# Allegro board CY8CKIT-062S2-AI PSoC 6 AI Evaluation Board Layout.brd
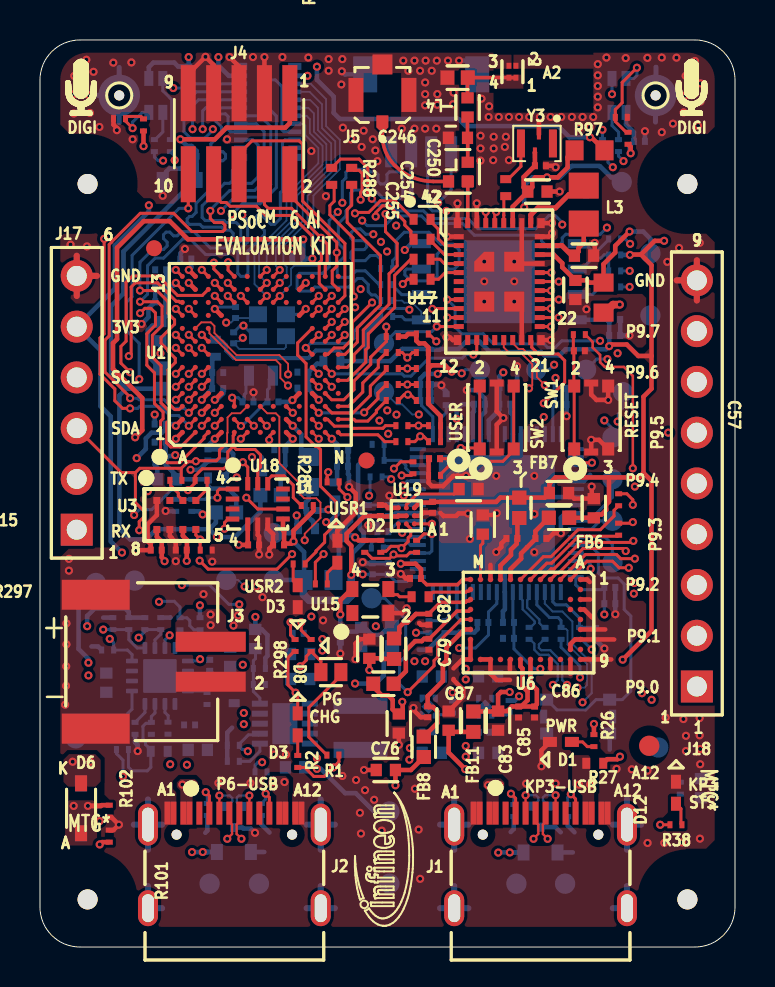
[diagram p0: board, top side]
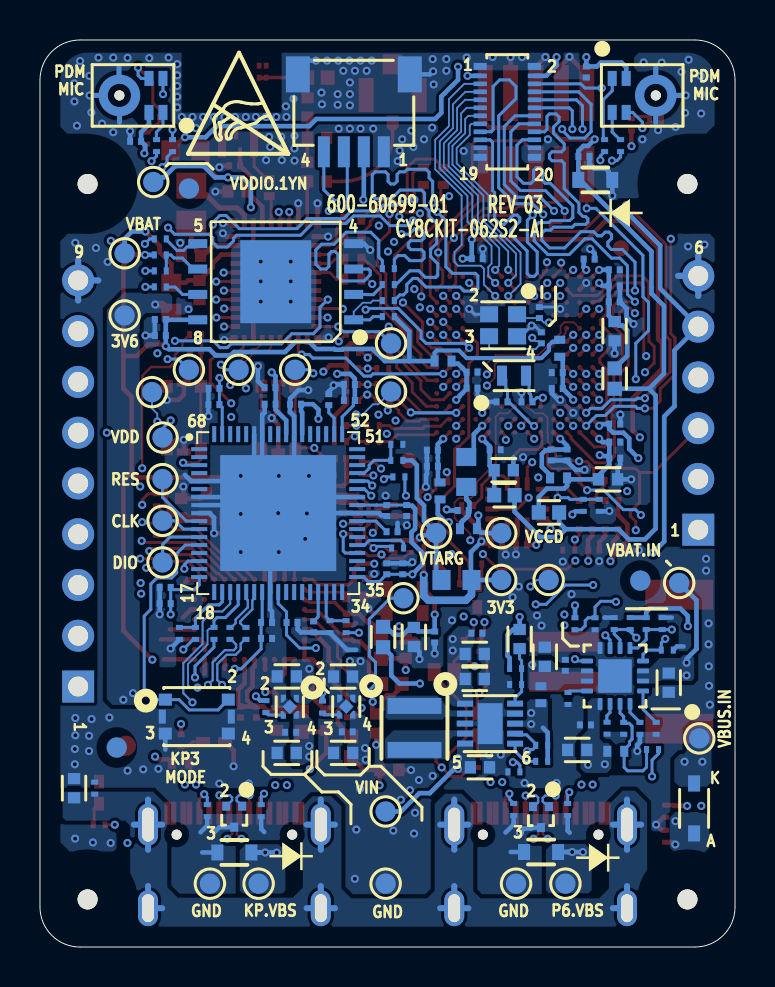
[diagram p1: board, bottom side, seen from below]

Outline 34.76 x 45.38 mm; copper layers: TOP, L02_GND1, L03_SIG1, L04_SIG2, L05_GND2, BOTTOM. Coordinates in mm from the lower left corner of the outline.
Outline path: 0,43.38 arc(0.59,44.8) 2,45.38 32.76,45.38 arc(34.18,44.8) 34.76,43.38 34.76,2 arc(34.18,0.59) 32.76,0 2,0 arc(0.59,0.59) 0,2 0,43.38

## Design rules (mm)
constraint set DEFAULT: min track width 0.15
net group DP_KP_USB_D: nets KP_USB_DM KP_USB_DP
net group KP_USB: nets N17581130 N17581131
net group P6_USB: nets P6_USB_DM P6_USB_DP
net group QSPI_DATA0_P11_6: nets N17289581 QSPI_DATA0_P11_6
net group QSPI_DATA1_P11_5: nets N17289597 QSPI_DATA1_P11_5
net group QSPI_DATA2_P11_4: nets N17289613 QSPI_DATA2_P11_4
net group QSPI_DATA3_P11_3: nets N17289629 QSPI_DATA3_P11_3
net group DEFAULT_1_5W: nets N17073640 N17073643 N17073646 N17073649 N17073652 N17073655 P5LP_XRES QSPI_CLK_P11_7 SDIO_CLK SDIO_CMD SDIO_DATA0 SDIO_DATA1 SDIO_DATA2 SDIO_DATA3
net group NON-IMPEDANCE: nets N17332695 N17332709 P8_0 P8_1 P8_2 P8_3 P8_4 P8_5 P9_0 P9_1 P9_2 P9_3 P9_4 P9_5 P9_6 P9_7
net group POWER: nets GND_EARTH KP_VBUS N17065875 N17305257 N17305261 N17462113 USB_V_SENSE VBACKUP VBAT VBAT_IN VBUCK VBUS_IN VCC_1V8 VCC_3V3 VCC_3V6 VCCD VDD_NS VDDA VDDA_RADAR VDDD VDDD_RADAR VDDIO0 VDDIO2 VDDIO_1YN VDDLF_RADAR VDDPLL_RADAR VDDRF_RADAR VDDUSB VDDVCO_RADAR VIN VREF VTARG_MEAS
net group QSPI_CLK_P11_7: nets N17531826
net group RF_50E_L2: nets ANT0 ANT1 ANT2 N17332525
net group SDHC: nets SDHC_CLK SDHC_CMD SDHC_DATA00 SDHC_DATA01 SDHC_DATA02 SDHC_DATA03 SDHC_DATA10 SDHC_DATA11 SDHC_DATA12 SDHC_DATA13
nets with their own width: min track width 0.229; nets GND_SIGNAL

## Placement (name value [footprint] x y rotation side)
A2  2450AT07A0100T  [ANT_2450AT07A0100]  23.63 43.79 0 top
C1  0.1uF  [CAPC0603_0201N]  8.49 14.09 90 bottom
C2  4.7uF  [CAPC1005_0402N]  9.51 14.52 90 bottom
C3  1uF  [CAPC1005_0402N]  7.89 9.86 0 bottom
C4  0.1uF  [CAPC0603_0201N]  7.48 11.11 0 bottom
C5  4.7uF  [CAPC1005_0402N]  3.32 13.23 270 bottom
C6  10nF  [CAPC1005_0402N]  33.06 7.95 90 bottom
C7  1uF  [CAPC1005_0402N]  19.6 9.71 0 bottom
C8  0.1uF  [CAPC0603_0201N]  19.39 10.76 0 bottom
C9  10uF  [CAPC1005_0402N]  12.76 8.99 180 bottom
C10  10uF  [CAPC1005_0402N]  13.02 13.41 180 bottom
C11  10uF  [CAPC1005_0402N]  13.02 14.66 180 bottom
C12  1uF  [CAPC1005_0402N]  19.6 13.53 0 bottom
C13  1uF  [CAPC1005_0402N]  22.42 9.71 0 bottom
C14  0.1uF  [CAPC0603_0201N]  22.22 10.74 0 bottom
C15  1uF  [CAPC1005_0402N]  22.41 13.54 0 bottom
C16  1uF  [CAPC0603_0201N]  23.43 15.44 180 bottom
C17  0.1uF  [CAPC0603_0201N]  23.43 16.24 180 bottom
C18  1uF  [CAPC0603_0201N]  16.62 18.92 90 bottom
C19  0.1uF  [CAPC0603_0201N]  17.42 18.92 90 bottom
C20  1uF  [CAPC0603_0201N]  16.42 21.84 270 bottom
C21  0.1uF  [CAPC0603_0201N]  17.42 21.84 270 bottom
C22  1uF  [CAPC0603_0201N]  28.5 17.18 0 bottom
C23  0.1uF  [CAPC0603_0201N]  28.5 17.99 0 bottom
C24  1uF  [CAPC0603_0201N]  20.32 27.39 90 bottom
C25  1uF  [CAPC0603_0201N]  22.16 16.24 180 bottom
C26  0.1uF  [CAPC0603_0201N]  21.98 27.16 0 bottom
C27  1uF  [CAPC0603_0201N]  26.06 27.95 0 bottom
C28  0.1uF  [CAPC0603_0201N]  26.06 27.14 0 bottom
C29  1uF  [CAPC0603_0201N]  19.29 28.14 0 bottom
C30  0.1uF  [CAPC0603_0201N]  19.29 27.34 0 bottom
C31  1uF  [CAPC0603_0201N]  23.26 27.99 0 bottom
C32  0.1uF  [CAPC0603_0201N]  23.25 27.16 0 bottom
C33  1uF  [CAPC0603_0201N]  17.15 20.78 180 bottom
C34  1uF  [CAPC0603_0201N]  21.07 16.02 270 bottom
C35  4.7uF  [CAPC0603_0201N]  13.6 21.84 0 bottom
C36  10uF  [CAPC1005_0402N]  11.57 23.86 180 bottom
C37  1uF  [CAPC0603_0201N]  7.29 34.42 180 bottom
C38  10uF  [CAPC1005_0402N]  6.35 23.4 180 bottom
C39  1uF  [CAPC0603_0201N]  6.01 26.16 180 bottom
C40  10uF  [CAPC1005_0402N]  6.02 30.81 270 bottom
C41  0.1uF  [CAPC0603_0201N]  15.14 24.86 0 bottom
C42  1uF  [CAPC0603_0201N]  15.13 24.05 0 bottom
C43  0.1uF  [CAPC0603_0201N]  8.4 24.62 270 bottom
C44  1uF  [CAPC0603_0201N]  9.2 24.62 270 bottom
C45  0.1uF  [CAPC0603_0201N]  13.15 27.96 180 bottom
C46  1uF  [CAPC0603_0201N]  13.15 28.76 180 bottom
C47  0.1uF  [CAPC0603_0201N]  6.04 33.88 180 bottom
C48  1uF  [CAPC0603_0201N]  6.04 32.28 180 bottom
C49  0.1uF  [CAPC0603_0201N]  6.04 33.08 180 bottom
C50  0.1uF  [CAPC0603_0201N]  6.01 25.26 180 bottom
C51  1uF  [CAPC0603_0201N]  6.01 24.46 180 bottom
C52  0.1uF  [CAPC0603_0201N]  12.89 34.44 180 bottom
C53  0.1uF  [CAPC0603_0201N]  8.89 27.94 0 bottom
C54  1uF  [CAPC0603_0201N]  8.89 28.74 0 bottom
C55  0.1uF  [CAPC0603_0201N]  12 24.88 180 bottom
C56  1uF  [CAPC0603_0201N]  7.56 39.56 180 bottom
C57  0.1uF  [CAPC0603_0201N]  26.98 29.83 0 top
C58  0.1uF  [CAPC0603_0201N]  19.73 24.43 180 top
C60  22pF  [CAPC0603_0201N]  10.4 27.28 180 bottom
C61  22pF  [CAPC0603_0201N]  11.65 27.28 180 bottom
C62  10pF  [CAPC0603_0201N]  9.78 31.74 90 bottom
C63  10pF  [CAPC0603_0201N]  9.69 30.48 90 bottom
C66  0.1uF  [CAPC0603_0201N]  5.81 19.86 180 top
C67  0.1uF  [CAPC0603_0201N]  7.07 19.86 180 top
C68  0.1uF  [CAPC0603_0201N]  7.44 43.78 270 bottom
C71  0.1uF  [CAPC0603_0201N]  29.98 40.31 0 bottom
C72  10uF  [CAPC1005_0402N]  27.7 21.95 90 top
C73  1uF  [CAPC0603_0201N]  25.06 20.44 0 top
C74  10uF  [CAPC1005_0402N]  25.96 22.71 0 top
C75  1uF  [CAPC0603_0201N]  23.6 20.44 180 top
C76  10uF  [CAPC1005_0402N]  17.3 8.86 180 top
C77  1uF  [CAPC0603_0201N]  19.39 11.77 270 top
C78  10uF  [CAPC1005_0402N]  17.95 11.18 270 top
C79  1uF  [CAPC0603_0201N]  19.45 15.15 270 top
C80  0.47uF  [CAPC1005_0402N]  22.15 21.14 270 top
C81  10uF  [CAPC1005_0402N]  16.47 14.92 90 top
C82  1uF  [CAPC0603_0201N]  19.45 16.4 270 top
C83  10uF  [CAPC1005_0402N]  22.91 11.32 270 top
C84  1uF  [CAPC0603_0201N]  18.78 18.44 180 top
C85  1uF  [CAPC0603_0201N]  23.94 11.76 270 top
C86  1uF  [CAPC0603_0201N]  24.74 11.76 270 top
C87  10uF  [CAPC1005_0402N]  20.44 11.32 90 top
C88  10uF  [CAPC1005_0402N]  16.06 15.51 270 bottom
C89  1uF  [CAPC0603_0201N]  15.02 15.51 270 bottom
C92  0.1uF  [CAPC0603_0201N]  28.74 31.4 0 bottom
C93  1uF  [CAPC0603_0201N]  28.74 30.6 0 bottom
C99  2.2uF  [CAPC1005_0402N]  24.88 37.8 0 top
C115  0.1uF  [CAPC0603_0201N]  17.02 21.84 90 top
C116  0.1uF  [CAPC0603_0201N]  10.68 20.12 180 top
C119  0.1uF  [CAPC0603_0201N]  19.63 22 270 top
C121  0.1uF  [CAPC0603_0201N]  11.93 20.12 180 top
C245  2.2uF  [CAPC1005_0402N]  21.44 22.91 0 top
C246  6.8pF  [CAPC1005_0402N]  21.39 42 90 top
C247  4.7uF  [CAPC1005_0402N]  26.78 32.87 270 top
C248  4.7uF  [CAPC1005_0402N]  27.21 34.59 0 top
C249  1uF  [CAPC0603_0201N]  25.03 39.09 0 top
C250  1.2pF  [CAPC1005_0402N]  20.9 40.48 180 top
C253  150pF  [CAPC1005_0402N]  10.77 15.41 270 bottom
C254  6.8pF  [CAPC1005_0402N]  21.39 38.78 90 top
C255  6.8pF  [CAPC1005_0402N]  20.91 38.3 0 top
C256  0.1uF  [CAPC0603_0201N]  12.91 15.7 180 bottom
D1  5988A10107F  [LEDC1005_0402Q]  26.05 10.26 180 top
D2  5988A10107F  [LEDC1005_0402Q]  14.87 19.78 90 top
D3  5988A10107F  [LEDC1005_0402Q]  12.89 17.55 270 top
D4  T5V0S5A-7  [SODFL1608X77N]  9.7 4.75 180 bottom
D5  BAS3010B03WE6327HTSA1  [SOD2512X110N]  2.05 6.93 270 bottom
D6  BAS3010B03WE6327HTSA1  [SOD2512X110N]  2.06 6.94 270 top
D8  LTST-C281KGKT  [LEDC1005X35N_GN_LITEON]  14.55 13.75 0 top
D9  ESD5V0D5-TP  [SODFL1608X77N]  6.99 38.38 0 bottom
D10  T5V0S5A-7  [SODFL1608X77N]  25.04 4.73 180 bottom
D11  5988A10107F  [LEDC1005_0402Q]  12.89 11.14 90 top
D12  5988A10107F  [LEDC1005_0402Q]  31.81 7.72 90 top
FB3  600 OHM  [INDC1005_0402M]  11.53 22.6 180 bottom
FB4  600 OHM  [INDC1005_0402M]  9.31 21.74 180 bottom
FB5  600 OHM  [INDC1005_0402M]  6.02 28.44 270 bottom
FB6  600 OHM  [INDC1005_0402M]  25.96 21.48 180 top
FB7  600 OHM  [INDC1005_0402M]  23.97 21.98 270 top
FB8  600 OHM  [INDC1005_0402M]  19.19 10.02 90 top
FB9  600 OHM  [INDC1005_0402M]  17.18 13.17 0 top
FB10  600 OHM  [INDC1005_0402M]  17.71 14.92 90 top
FB11  600 OHM  [INDC1005_0402M]  21.68 11.27 90 top
FB12  600 OHM  [INDC1005_0402M]  17.6 15.51 90 bottom
J1  629722000214  [GCT_USB4105-GF-A]  25.04 3.02 0 top
J2  629722000214  [GCT_USB4105-GF-A]  9.72 3.02 0 top
J3  620102131822  [JST_S2B-PH-SM4-TB-LF-SN]  5.09 14.28 90 top
J4  HDR 5x2  [SAMT_FTSH-105-XX-X-DV-K]  9.96 40.69 180 top
J5  A-1JB  [AMP_A-1JB_ALT1]  17.13 42.63 0 top
J15  DF40C-20DP-0.4V(51)  [HIROSE_DF40C-20DP-0P4V]  11.39 41.79 270 bottom
J16  665104131822  [JST_SM04B-SRSS-TB]  19.07 42.24 0 bottom
J17  PRPC006SFAN-RC  [SULLINS_PRPC006SFAN-RC]  1.84 20.88 90 top
J18  PRPC009SFAN-RC  [SULLINS_PRPC009SFAN-RC]  32.85 13.03 90 top
L1  2.2uH  [IND_NR3015T2R2M]  16.03 10.96 270 bottom
L2  2.2uH  [INDC1608_0603N]  13.44 23.77 270 bottom
L3  2.2uH  [INDC2012_0805N]  27.2 37.14 90 top
L4  6.8nH  [INDC1005_0402M]  20.89 43.5 180 top
NOREF  -  []  6.14 38.38 0 top
NOREF#2  -  []  8.47 6.7 0 top
NOREF#3  -  []  17.57 39.79 0 top
NOREF#4  -  []  10.53 30.23 0 top
NOREF#5  -  []  4.45 12.01 0 top
NOREF#6  -  []  1.29 10.33 90 top
NOREF#7  -  []  11 10.18 0 top
NOREF#8  -  []  10.95 9.88 90 top
NOREF#9  -  []  16.27 43.66 0 top
NOREF#10  -  []  21.99 28.07 0 top
NOREF#11  -  []  17.68 20.93 90 top
NOREF#12  -  []  1.32 5.98 0 top
NOREF#13  -  []  2.79 10.93 90 top
NOREF#14  -  [unnamed#2]  32.38 38.18 0 top
NOREF#15  -  []  2.6 44.15 0 top
NOREF#16  -  []  8.07 20.62 90 top
NOREF#17  -  []  7.97 6.7 0 top
NOREF#18  -  []  1.32 5.98 90 top
NOREF#19  -  []  16.03 9.86 90 top
NOREF#20  -  []  26.72 28.07 0 top
NOREF#21  -  []  20.72 1.94 90 top
NOREF#22  -  []  25.19 11.53 0 top
NOREF#23  -  []  26.2 18.72 90 top
NOREF#24  -  []  20.57 6.69 0 top
NOREF#25  -  []  1.84 28.5 90 top
NOREF#26  -  []  9.39 23.16 0 top
NOREF#27  -  []  23.29 6.7 0 top
NOREF#28  -  []  9.63 22.91 0 top
NOREF#29  -  []  17.68 20.93 0 top
NOREF#30  -  []  18.65 19.46 90 top
NOREF#31  -  []  3.11 22 0 top
NOREF#32  -  []  8.54 13.28 90 top
NOREF#33  -  []  25.27 10.08 90 top
NOREF#34  -  []  18.72 21.17 90 top
NOREF#35  -  []  22.84 24.77 90 top
NOREF#36  -  []  25.34 10.68 90 top
NOREF#37  -  []  5.4 1.94 0 top
NOREF#38  -  []  2.79 10.93 90 top
NOREF#39  -  []  12.68 28.48 90 top
NOREF#40  -  []  14.19 -0.66 90 top
NOREF#41  -  []  14.48 9.41 90 top
NOREF#42  -  []  25.69 4.31 90 top
NOREF#43  -  []  26.03 18.39 0 top
NOREF#44  -  []  17.57 39.79 90 top
NOREF#45  -  []  32.15 36.99 90 top
NOREF#46  -  []  7.55 12.01 90 top
NOREF#47  -  []  21.39 24.84 90 top
NOREF#48  -  []  29.51 -0.66 90 top
NOREF#49  -  []  5.25 6.69 0 top
NOREF#50  -  [unnamed#2]  2.38 2.38 0 top
NOREF#51  -  []  5.4 1.94 90 top
NOREF#52  -  []  4.6 13.31 90 top
NOREF#53  -  []  5.85 20.89 90 top
NOREF#54  -  []  17.57 39.79 0 top
NOREF#55  -  []  25.69 5.16 0 top
NOREF#56  -  []  29.51 -0.66 90 top
NOREF#57  -  []  2.6 40.07 90 top
NOREF#58  -  []  4.6 14.31 0 top
NOREF#59  -  [unnamed#2]  30.47 10.07 0 top
NOREF#60  -  []  0 43.38 0 top
NOREF#61  -  []  6.34 37.95 0 top
NOREF#62  -  []  14.48 9.41 0 top
NOREF#63  -  []  21.53 16.39 90 top
NOREF#64  -  []  17.52 16.51 90 top
NOREF#65  -  []  16.07 44.36 0 top
NOREF#66  -  []  25.34 12.38 0 top
NOREF#67  -  []  21.2 25.22 0 top
NOREF#68  -  []  10.35 5.18 90 top
NOREF#69  -  []  15.05 13.5 90 top
NOREF#70  -  []  2.05 5.68 90 top
NOREF#71  -  []  10.9 30.56 90 top
NOREF#72  -  []  22.07 40.11 90 top
NOREF#73  -  []  14.05 14 0 top
NOREF#74  -  []  10.95 12.48 0 top
NOREF#75  -  []  12.39 20.91 90 top
NOREF#76  -  []  32.85 20.65 90 top
NOREF#77  -  []  25.27 12.98 0 top
NOREF#78  -  []  10.39 23.18 0 top
NOREF#79  -  []  15.52 18.11 0 top
NOREF#80  -  []  146.08 294.67 0 top
NOREF#81  -  []  2.78 5.99 90 top
NOREF#82  -  []  -21.25 -36.06 0 top
NOREF#83  -  []  27.57 24.77 90 top
NOREF#84  -  []  15.62 16.71 90 top
NOREF#85  -  []  26.72 24.92 90 top
NOREF#86  -  []  18.32 21.97 0 top
NOREF#87  -  []  26.12 24.84 90 top
NOREF#88  -  []  21.39 28.14 0 top
NOREF#89  -  []  1.29 18.23 0 top
NOREF#90  -  []  26.12 28.14 0 top
NOREF#91  -  []  32.15 41.07 0 top
NOREF#92  -  []  14.19 -0.66 90 top
NOREF#93  -  []  15.62 16.71 0 top
NOREF#94  -  []  10.35 5.18 0 top
NOREF#95  -  []  34.13 0.54 0 top
NOREF#96  -  []  5.57 22.62 0 top
NOREF#97  -  [unnamed#2]  2.38 38.18 0 top
NOREF#98  -  []  20.72 1.94 0 top
NOREF#99  -  []  10.9 31.66 0 top
NOREF#100  -  []  1.33 5.99 0 top
NOREF#101  -  []  2.38 0 90 top
NOREF#102  -  []  6.34 37.95 90 top
NOREF#103  -  []  8.85 4.75 0 top
NOREF#104  -  []  2.06 5.69 90 top
NOREF#105  -  []  122.33 85.74 0 top
NOREF#106  -  []  6.5 20.89 0 top
NOREF#107  -  [unnamed#2]  32.38 2.38 0 top
NOREF#108  -  []  34.12 14.15 0 top
NOREF#109  -  []  13.5 10.68 90 top
NOREF#110  -  []  21.99 24.92 90 top
NOREF#111  -  []  24.19 4.73 0 top
NOREF#112  -  []  23.79 6.7 0 top
NOREF#113  -  []  5.25 12.16 90 top
NOREF#114  -  []  57.28 11.61 90 top
NOREF#115  -  [unnamed#2]  27.31 37.95 180 bottom
NOREF#116  -  [unnamed#2]  30.92 9.98 180 bottom
NOREF#117  -  [unnamed#2]  4.74 18.33 180 bottom
R1  1K  [RESC0603_0201N]  14.65 9.6 0 top
R2  1K  [RESC0603_0201N]  12.89 9.29 270 top
R3  10K  [RESC0603_0201N]  5.24 16.18 90 bottom
R4  10K  [RESC0603_0201N]  4.44 16.18 90 bottom
R5  5.1K  [RESC0603_0201N]  26.4 6.83 270 bottom
R6  5.1K  [RESC0603_0201N]  23.69 6.83 270 bottom
R7  100K  [RESC0603_0201N]  32.03 7.95 90 bottom
R8  10K  [RESC0603_0201N]  3.94 10.94 90 bottom
R9  10K  [RESC0603_0201N]  6.4 10.95 90 bottom
R10  10K  [RESC0603_0201N]  3.39 14.86 0 bottom
R11  10K  [RESC0603_0201N]  6.04 16.18 270 bottom
R12  10K  [RESC0603_0201N]  3.64 16.18 270 bottom
R13  10K  [RESC1005_0402N]  5.96 9.79 0 bottom
R14  3.01K  [RESC0603_0201N]  5.57 10.94 270 bottom
R15  1K  [RESC0603_0201N]  8.35 12.44 270 bottom
R16  4.7K  [RESC0603_0201N]  4.76 10.94 270 bottom
R17  5.1K  [RESC0603_0201N]  11.07 6.88 270 bottom
R18  5.1K  [RESC0603_0201N]  8.37 6.88 270 bottom
R19  4.7K  [RESC0603_0201N]  20.63 12.01 270 bottom
R20  4.7K  [RESC0603_0201N]  9.67 9.29 0 bottom
R21  560K  [RESC0603_0201N]  10.97 13.94 180 bottom
R22  4.7K  [RESC0603_0201N]  9.67 10.09 0 bottom
R23  90.9K  [RESC0603_0201N]  10.97 13.14 0 bottom
R24  4.7K  [RESC0603_0201N]  11.06 8.76 0 bottom
R25  4.7K  [RESC0603_0201N]  23.46 12.03 270 bottom
R26  1K  [RESC0603_0201N]  27.71 10.33 270 top
R27  0 OHM  [RESC1005_0402N]  27.75 9.19 180 top
R28  49.9K  [RESC0603_0201N]  16.91 24.35 0 bottom
R29  49.9K  [RESC0603_0201N]  16.91 25.15 0 bottom
R30  15K  [RESC0603_0201N]  19.45 16.03 90 bottom
R31  30K  [RESC0603_0201N]  20.25 16.03 90 bottom
R33  15K  [RESC0603_0201N]  26.99 15.69 90 bottom
R34  4.7K  [RESC0603_0201N]  26.06 15.69 270 bottom
R35  22 OHM  [RESC0603_0201N]  25.26 15.69 90 bottom
R36  30K  [RESC0603_0201N]  27.79 15.69 90 bottom
R37  22 OHM  [RESC0603_0201N]  24.46 15.69 90 bottom
R38  560 OHM  [RESC0603_0201N]  31.81 6.12 180 top
R39  0 OHM  [RESC1608_0603N]  13.93 18.37 0 bottom
R40  0 OHM  [RESC1005_0402N]  13.33 20.93 180 bottom
R41  4.7K  [RESC0603_0201N]  26.98 30.64 180 top
R42  47K  [RESC0603_0201N]  19.73 26.09 180 top
R43  47K  [RESC0603_0201N]  19.12 28.14 180 top
R44  47K  [RESC0603_0201N]  19.12 28.94 180 top
R45  47K  [RESC0603_0201N]  19.12 29.74 180 top
R46  47K  [RESC0603_0201N]  19.73 25.29 180 top
R47  47K  [RESC0603_0201N]  17.62 30.54 180 top
R48  33 OHM  [RESC0603_0201N]  18.1 26.09 180 top
R49  33 OHM  [RESC0603_0201N]  17.62 27.34 180 top
R50  47K  [RESC0603_0201N]  19.12 27.34 180 top
R51  33 OHM  [RESC0603_0201N]  17.62 28.14 180 top
R52  33 OHM  [RESC0603_0201N]  17.62 28.94 180 top
R53  33 OHM  [RESC0603_0201N]  17.62 29.74 180 top
R54  33 OHM  [RESC0603_0201N]  18.1 25.29 180 top
R55  1K  [RESC0603_0201N]  19.73 23.6 0 top
R56  0 OHM  [RESC1005_0402N]  19.11 35.41 180 top
R57  0 OHM  [RESC1005_0402N]  19.11 36.41 180 top
R58  47K  [RESC0603_0201N]  19.12 30.67 0 top
R59  0 OHM  [RESC1005_0402N]  19.11 34.41 180 top
R60  0 OHM  [RESC1005_0402N]  19.11 33.41 180 top
R62  1K  [RESC0603_0201N]  14.07 18.17 180 top
R63  1K  [RESC0603_0201N]  12.96 19.17 0 top
R64  0 OHM  [RESC0603_0201N]  8.06 23.35 180 top
R65  0 OHM  [RESC0603_0201N]  6.8 23.35 0 top
R66  100K  [RESC0603_0201N]  8.32 19.86 0 top
R71  100 OHM  [RESC0603_0201N]  6.52 40.1 270 bottom
R72  0 OHM  [RESC0603_0201N]  5.72 40.1 270 bottom
R73  0 OHM  [RESC0603_0201N]  5.18 41.13 90 top
R74  0 OHM  [RESC0603_0201N]  3.98 41.45 180 top
R79  100 OHM  [RESC0603_0201N]  28.93 40.1 270 bottom
R80  0 OHM  [RESC0603_0201N]  28.13 40.1 270 bottom
R81  0 OHM  [RESC0603_0201N]  29.41 40.46 90 top
R82  0 OHM  [RESC0603_0201N]  29.08 41.51 0 top
R83  150 OHM  [RESC1005_0402N]  19.01 17.53 0 top
R84  10K  [RESC0603_0201N]  17.34 31.54 0 bottom
R85  10K  [RESC0603_0201N]  28.74 34.63 180 bottom
R86  0 OHM  [RESC0603_0201N]  17.34 32.34 180 bottom
R87  33 OHM  [RESC0603_0201N]  28.74 33.83 0 bottom
R88  33 OHM  [RESC0603_0201N]  28.74 35.43 0 bottom
R89  33 OHM  [RESC0603_0201N]  17.34 33.14 180 bottom
R90  33 OHM  [RESC0603_0201N]  17.34 33.94 180 bottom
R91  33 OHM  [RESC0603_0201N]  28.74 33.03 0 bottom
R96  0 OHM  [RESC1608_0603N]  28.19 32.49 90 top
R97  0 OHM  [RESC1608_0603N]  27.48 39.86 180 top
R100  0 OHM  [RESC1005_0402N]  23.29 37.99 270 top
R101  100K  [RESC0603_0201N]  3.47 5.55 90 top
R102  100K  [RESC0603_0201N]  3.47 6.8 270 top
R275  0 OHM  [RESC1005_0402N]  14.75 22.82 90 bottom
R277  0 OHM  [RESC1005_0402N]  8.77 29.96 270 bottom
R278  0 OHM  [RESC1005_0402N]  14.6 29.32 180 bottom
R279  15K  [RESC0603_0201N]  8 16.17 270 bottom
R280  30K  [RESC0603_0201N]  7 16.17 90 bottom
R281  4.7K  [RESC0603_0201N]  17.05 20.05 90 top
R282  4.7K  [RESC0603_0201N]  16.25 20.05 90 top
R283  0 OHM  [RESC0603_0201N]  4.12 9.88 180 bottom
R284  0 OHM  [RESC1005_0402N]  8.82 23.47 0 bottom
R285  0 OHM  [RESC0603_0201N]  13.37 22.09 0 top
R286  0 OHM  [RESC0603_0201N]  7.59 22.1 270 bottom
R287  0 OHM  [RESC0603_0201N]  6.79 22.1 270 bottom
R288  0 OHM  [RESC1005_0402N]  15.59 38.56 270 top
R289  0 OHM  [RESC1005_0402N]  14.59 38.56 270 top
R290  0 OHM  [RESC1005_0402N]  9.71 12.62 90 bottom
R291  0 OHM  [RESC0603_0201N]  28.94 22.38 270 top
R292  0 OHM  [RESC0603_0201N]  14.66 23.27 0 top
R293  0 OHM  [RESC0603_0201N]  18.65 23.98 270 top
R294  0 OHM  [RESC0603_0201N]  16.81 23.52 0 bottom
R295  0 OHM  [RESC0603_0201N]  16.87 19.96 0 bottom
R296  0 OHM  [RESC0603_0201N]  18.84 20.05 270 top
R297  30K  [RESC0603_0201N]  13.56 15.09 270 top
R298  30K  [RESC0603_0201N]  12.76 15.09 270 top
R299  0 OHM  [RESC0603_0201N]  28.94 20.9 270 top
SW1  435171014816  [SW_435171014816]  27.57 26.49 90 top
SW2  435171014816  [SW_435171014816]  22.84 26.49 90 top
SW3  435171014816  [SW_435171014816]  26.92 11.53 180 bottom
TP1  TP_SMD  [TP102C]  23.83 3.17 180 bottom
TP2  TP_SMD  [TP102C]  10.95 3.17 180 bottom
TP3  TP_SMD  [TP102C]  8.48 3.17 180 bottom
TP4  TP_SMD  [TP102C]  26.26 3.17 180 bottom
TP5  TP_SMD  [TP102C]  28.63 25.49 180 bottom
TP6  TP_SMD  [TP102C]  17.47 3.17 180 bottom
TP7  TP_SMD  [TP102C]  28.63 23.41 180 bottom
TP8  TP_SMD  [TP102C]  28.63 19.24 180 bottom
TP9  TP_SMD  [TP102C]  28.63 21.32 180 bottom
TP10  TP_SMD  [TP102C]  11.69 18.37 180 bottom
TP11  TP_SMD  [TP102C]  14.95 20.71 180 bottom
TP12  TP_SMD  [TP102C]  11.69 20.71 180 bottom
TP16  TP_SMD  [TP102C]  16.59 17.45 180 bottom
TP17  TP_SMD  [TP102C]  29.16 27.76 180 bottom
TP19  TP_SMD  [TP102C]  17.21 27.79 180 bottom
TP23  TP_SMD  [TP102C]  30.53 34.71 180 bottom
TP24  TP_SMD  [TP102C]  29.1 38.27 180 bottom
TP26  TP_SMD  [TP102C]  17.21 30.2 180 bottom
TP27  TP_SMD  [TP102C]  24.83 28.88 180 bottom
TP28  TP_SMD  [TP102C]  22.01 28.88 180 bottom
TP29  TP_SMD  [TP102C]  27.31 28.88 180 bottom
TP30  TP_SMD  [TP102C]  1.79 10.44 180 bottom
TP31  TP_SMD  [TP102C]  9.32 18.37 180 bottom
TP32  TP_SMD  [TP102C]  30.53 31.6 180 bottom
TP33  TP_SMD  [TP102C]  17.47 6.78 180 bottom
TP34  TP_SMD  [TP102C]  2.79 18.21 180 bottom
U1  CY8C624ABZI-S2D44  [BGA124C65P13X13_900X900X100]  11.02 29.65 90 top
U2  CY8C5868LTI-LP039  [QFN40P800X800_68-H580N]  22.85 21.71 180 bottom
U3  DPS368XTSA1  [LGA8S145X65P2X4_200X250X110]  6.82 21.62 0 top
U4  IM72D128V01XTMA1  [MIC_IM73A135V01XTSA1]  4.64 42.61 270 bottom
U5  IM72D128V01XTMA1  [MIC_IM73A135V01XTSA1]  30.11 42.61 90 bottom
U6  BGT60TR13CE6327XUMA1  [VF2BGA40N50P9X12_500X650X90]  24.45 16.22 270 top
U7  S25HS512TFANHI010  [SON127P800X600_8-H410X350]  22.97 33.29 0 bottom
U8  BQ24074RGTT  [QFN50P300X300X100-17N_TI]  6 13.56 0 bottom
U9  ESD5V3U2U-03F  [SOTFL40P120X59-3N]  9.71 6.5 270 bottom
U11  RT6150BGQW  [DFN50P250X250X80-11N]  12.25 11.18 180 bottom
U15  80 MHz  [OSCCC200X160X80-4N]  16.52 17.31 0 top
U16  ESD5V3U2U-03F  [SOTFL40P120X59-3N]  25.05 6.52 270 bottom
U17  LBEE5KL1YN-814  [MOD-LBEE5KL1DX_4343]  22.97 33.29 0 top
U18  BMI270  [BOSCH_BMI323]  10.89 22.16 0 top
U19  BMM350  [BOSCH_BMM350]  18.32 21.57 180 top
U20  NCP115AMX330TBG  [DFN65P100X100X43-5N]  19.44 12.03 0 bottom
U21  NCP115AMX180TBG  [DFN65P100X100X43-5N]  22.27 12.02 0 bottom
Y1  32.768KHz  [XTAL_ABS05_1M6X1M]  11.05 28.59 180 bottom
Y2  24MHZ  [OSCCC205X165X60-4N]  11.6 31.11 0 bottom
Y3  SIT1533AI-H4-DCC-32.768E  [OSSCCC200X120X55-4N]  24.85 40.2 270 top

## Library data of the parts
A2 = ANT_2450AT07A0100
C1-C58 C60-C63 C66-C68 C71-C89 C92 C93 C99 C115 C116 C119 C121 C245-C250 C253-C256 = CAP-NP
D1-D3 D8 D11 D12 = DIO-LED
D4 D9 D10 = DIO-TVS
D5 D6 = DIO-SCHOTTKY
FB3-FB12 = FB
J1 J2 = USB_TYPE_C-16PIN_4SH
J3 = PLG-2-J_SH1_2
J4 = PLG-10-ODD-EVEN-J
J5 = A-1JB
J15 = PLG-20-ODD-EVEN-4SH-J
J16 = PLG-4-2SH-J
J17 = PLG-6-J
J18 = PLG-9-J
L1-L4 = IND
R1-R31 R33-R38 R40-R47 R50 R55-R60 R62-R66 R71-R74 R79-R86 R100-R102 R275 R277-R299 = RES
R39 R96 R97 = RES: User Part Number: Part No
R48 R49 R51-R54 R87-R91 = RES: signal model: DEFAULT_RESISTOR_33.000000OHM_1_2
SW1-SW3 = SWITCH-PB-12-34-G56
TP1-TP12 TP16 TP17 TP19 TP23 TP24 TP26-TP34 = TP_SMD
U1 = CY8C624ABZI-S2D44
U2 = CY8C5868LTI-LP039
U3 = IC_DPS368
U4 U5 = IC_IM72D128V01_4
U6 = IC_BGT60TR13C
U7 = IC_S25HS512TFANH: User Part Number: Part No
U8 = IC_BQ24074_0
U9 U16 = ESD5V3U2U-03F
U11 = IC_RT6150B_0
U15 = OSC-KC2016K
U17 = LBEE5KL1DX
U18 = IC_BMI270
U19 = IC_BMM350
U20 U21 = IC_NCP115AMX_0
Y1 = XTAL-2P
Y2 = XTAL-4P-2G4G
Y3 = OSC-SiT1533

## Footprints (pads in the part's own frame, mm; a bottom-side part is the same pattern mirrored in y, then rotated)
AMP_A-1JB_ALT1
  rect 0.75x1.7 smd: G1(-1.325,0) G3(1.325,0)
  rect 1x1 smd: G2(0,1.524)
  custom 0.15x0.15 smd: S(0,-1.399)
ANT_2450AT07A0100
  rect 0.25x0.3 smd: 1(0.175,-0.3) 2(0.175,0.3) 3(-0.175,0.3) 4(-0.175,-0.3)
BGA124C65P13X13_900X900X100
  round 0.8 smd: (-5.31,-5.31) (5.31,5.31)
  round 0.25 smd: A1(-3.9,3.9) A2(-3.25,3.9) A3(-2.6,3.9) A4(-1.95,3.9) A5(-1.3,3.9) A6(-0.65,3.9) A7(0,3.9) A8(0.65,3.9) A9(1.3,3.9) A10(1.95,3.9) A11(2.6,3.9) A12(3.25,3.9) A13(3.9,3.9) B1(-3.9,3.25) B2(-3.25,3.25) B3(-2.6,3.25) B4(-1.95,3.25) B5(-1.3,3.25) B6(-0.65,3.25) B7(0,3.25) B8(0.65,3.25) B9(1.3,3.25) B10(1.95,3.25) B11(2.6,3.25) B12(3.25,3.25) B13(3.9,3.25) C1(-3.9,2.6) C2(-3.25,2.6) C3(-2.6,2.6) C4(-1.95,2.6) C5(-1.3,2.6) C6(-0.65,2.6) C7(0,2.6) C8(0.65,2.6) C9(1.3,2.6) C10(1.95,2.6) C11(2.6,2.6) C12(3.25,2.6) C13(3.9,2.6) D1(-3.9,1.95) D2(-3.25,1.95) D3(-2.6,1.95) D4(-1.95,1.95) D10(1.95,1.95) D11(2.6,1.95) D12(3.25,1.95) D13(3.9,1.95) E1(-3.9,1.3) E2(-3.25,1.3) E3(-2.6,1.3) E11(2.6,1.3) E12(3.25,1.3) E13(3.9,1.3) F1(-3.9,0.65) F2(-3.25,0.65) F3(-2.6,0.65) F11(2.6,0.65) F12(3.25,0.65) F13(3.9,0.65) G1(-3.9,0) G2(-3.25,0) G3(-2.6,0) G11(2.6,0) G12(3.25,0) G13(3.9,0) H1(-3.9,-0.65) H2(-3.25,-0.65) H3(-2.6,-0.65) H11(2.6,-0.65) H12(3.25,-0.65) H13(3.9,-0.65) J1(-3.9,-1.3) J2(-3.25,-1.3) J3(-2.6,-1.3) J11(2.6,-1.3) J12(3.25,-1.3) J13(3.9,-1.3) K1(-3.9,-1.95) K2(-3.25,-1.95) K3(-2.6,-1.95) K4(-1.95,-1.95) K10(1.95,-1.95) K11(2.6,-1.95) K12(3.25,-1.95) K13(3.9,-1.95) L1(-3.9,-2.6) L2(-3.25,-2.6) L3(-2.6,-2.6) L4(-1.95,-2.6) L5(-1.3,-2.6) L6(-0.65,-2.6) L7(0,-2.6) L8(0.65,-2.6) L9(1.3,-2.6) L10(1.95,-2.6) L11(2.6,-2.6) L12(3.25,-2.6) L13(3.9,-2.6) M1(-3.9,-3.25) M2(-3.25,-3.25) M3(-2.6,-3.25) M4(-1.95,-3.25) M5(-1.3,-3.25) M6(-0.65,-3.25) M7(0,-3.25) M8(0.65,-3.25) M9(1.3,-3.25) M10(1.95,-3.25) M11(2.6,-3.25) M12(3.25,-3.25) M13(3.9,-3.25) N1(-3.9,-3.9) N2(-3.25,-3.9) N3(-2.6,-3.9) N4(-1.95,-3.9) N5(-1.3,-3.9) N6(-0.65,-3.9) N7(0,-3.9) N8(0.65,-3.9) N9(1.3,-3.9) N10(1.95,-3.9) N11(2.6,-3.9) N12(3.25,-3.9) N13(3.9,-3.9)
BOSCH_BMI323
  rect 0.675x0.25 smd: 1(-1.262,0.75) 2(-1.262,0.25) 3(-1.262,-0.25) 4(-1.262,-0.75) 8(1.262,-0.75) 9(1.262,-0.25) 10(1.262,0.25) 11(1.262,0.75)
  rect 0.25x0.675 smd: 5(-0.5,-1.012) 6(0,-1.012) 7(0.5,-1.012) 12(0.5,1.012) 13(0,1.012) 14(-0.5,1.012)
BOSCH_BMM350
  round 0.25 smd: A1(-0.4,0.4) A2(0,0.4) A3(0.4,0.4) B1(-0.4,0) B2(0,0) B3(0.4,0) C1(-0.4,-0.4) C2(0,-0.4) C3(0.4,-0.4)
CAPC0603_0201N
  rect 0.3x0.35 smd: 1(-0.275,0) 2(0.275,0)
CAPC1005_0402N
  rect 0.56x0.62 smd: 1(-0.48,0) 2(0.48,0)
DFN50P250X250X80-11N
  rect 0.8x0.3 smd: 1(-1.25,1) 2(-1.25,0.5) 3(-1.25,0) 4(-1.25,-0.5) 5(-1.25,-1) 6(1.25,-1) 7(1.25,-0.5) 8(1.25,0) 9(1.25,0.5) 10(1.25,1)
  rect 1.25x2.05 smd: H(0,0)
DFN65P100X100X43-5N
  custom 0.065x0.065 smd: 1(-0.325,-0.405) 2(0.325,-0.405) 3(0.325,0.405) 4(-0.325,0.405)
  rect 0.52x0.52 smd rot 45: 5(0,0)
GCT_USB4105-GF-A
  round 0.5 hole 0.65 unplated: (-2.89,2.605) (2.89,2.605)
  rect 0.3x1.15 smd: A1(-3.35,3.68) A4(-2.55,3.68) A5(-1.25,3.68) A6(-0.25,3.68) A7(0.25,3.68) A8(1.25,3.68) A9(2.55,3.68) A12(3.35,3.68) B1(3.05,3.68) B4(2.25,3.68) B5(1.75,3.68) B6(0.75,3.68) B7(-0.75,3.68) B8(-1.75,3.68) B9(-2.25,3.68) B12(-3.05,3.68)
  oval 1x2.1 hole 0.6x1.7: SH1(-4.32,3.105) SH2(4.32,3.105)
  oval 1x1.8 hole 0.6x1.4: SH3(-4.32,-1.075) SH4(4.32,-1.075)
HIROSE_DF40C-20DP-0P4V
  rect 0.23x0.66 smd: 1(-1.8,-1.355) 2(-1.8,1.355) 3(-1.4,-1.355) 4(-1.4,1.355) 5(-1,-1.355) 6(-1,1.355) 7(-0.6,-1.355) 8(-0.6,1.355) 9(-0.2,-1.355) 10(-0.2,1.355) 11(0.2,-1.355) 12(0.2,1.355) 13(0.6,-1.355) 14(0.6,1.355) 15(1,-1.355) 16(1,1.355) 17(1.4,-1.355) 18(1.4,1.355) 19(1.8,-1.355) 20(1.8,1.355)
  rect 0.35x0.66 smd: SH1(-2.275,-1.355) SH2(-2.275,1.355) SH3(2.275,-1.355) SH4(2.275,1.355)
IND_NR3015T2R2M
  rect 0.8x2.7 smd: 1(-1.1,0) 2(1.1,0)
INDC1005_0402M
  rect 0.7x0.72 smd: 1(-0.51,0) 2(0.51,0)
INDC1608_0603N
  rect 0.9x1 smd: 1(-0.75,0) 2(0.75,0)
INDC2012_0805N
  rect 1.3x1.5 smd: 1(-0.95,0) 2(0.95,0)
JST_S2B-PH-SM4-TB-LF-SN
  rect 1x3.5 smd: 1(1,-3.45) 2(-1,-3.45)
  rect 1.5x3.4 smd: SH1(3.35,2.3) SH2(-3.35,2.3)
JST_SM04B-SRSS-TB
  rect 0.6x1.55 smd: 1(-1.5,2.45) 2(-0.5,2.45) 3(0.5,2.45) 4(1.5,2.45)
  rect 1.2x1.8 smd: SH1(-2.8,-1.425) SH2(2.8,-1.425)
LEDC1005_0402Q
  rect 0.7x0.5 smd: A(-0.55,0) K(0.55,0)
LEDC1005X35N_GN_LITEON
  rect 0.65x0.9 smd: A(0.5,0) K(-0.5,0)
LGA8S145X65P2X4_200X250X110
  rect 0.35x0.35 smd: 1(-0.975,0.725) 2(-0.325,0.725) 3(0.325,0.725) 4(0.975,0.725) 5(0.975,-0.725) 6(0.325,-0.725) 7(-0.325,-0.725) 8(-0.975,-0.725)
MIC_IM73A135V01XTSA1
  round 0.5 hole 0.8 unplated: (0,0.68)
  rect 0.75x0.45 smd: 1(-0.85,-1.5) 2(-0.85,-0.8) 3(0.85,-1.5) 4(0.85,-0.8)
  round 0.2 smd: 5(0,1.48)
MOD-LBEE5KL1DX_4343
  rect 0.5x0.25 smd: 1(-2.025,2.25) 2(-2.025,1.8) 3(-2.025,1.35) 4(-2.025,0.9) 5(-2.025,0.45) 6(-2.025,0) 7(-2.025,-0.45) 8(-2.025,-0.9) 9(-2.025,-1.35) 10(-2.025,-1.8) 11(-2.025,-2.25) 22(2.025,-2.25) 23(2.025,-1.8) 24(2.025,-1.35) 25(2.025,-0.9) 26(2.025,-0.45) 27(2.025,0) 28(2.025,0.45) 29(2.025,0.9) 30(2.025,1.35) 31(2.025,1.8) 32(2.025,2.25)
  rect 0.375x0.5 smd: 12(-2.088,-2.925) 21(2.088,-2.925) 33(2.088,2.925) 42(-2.088,2.925)
  rect 0.25x0.5 smd: 13(-1.575,-2.925) 14(-1.125,-2.925) 15(-0.675,-2.925) 16(-0.225,-2.925) 17(0.225,-2.925) 18(0.675,-2.925) 19(1.125,-2.925) 20(1.575,-2.925) 34(1.575,2.925) 35(1.125,2.925) 36(0.675,2.925) 37(0.225,2.925) 38(-0.225,2.925) 39(-0.675,2.925) 40(-1.125,2.925) 41(-1.575,2.925)
  custom 0.25x0.25 smd: 43(-0.75,1)
  rect 1x1 smd: 44(-0.75,-1) 45(0.75,1) 46(0.75,-1)
OSCCC200X160X80-4N
  rect 0.6x0.8 smd: 1(-0.9,-0.6) 2(0.9,-0.6) 3(0.9,0.6) 4(-0.9,0.6)
OSCCC205X165X60-4N
  rect 0.9x0.8 smd: 1(-0.7,-0.55) 2(0.7,-0.55) 3(0.7,0.55) 4(-0.7,0.55)
OSSCCC200X120X55-4N
  rect 0.5x0.2 smd: G(-0.45,0.1) P(0.45,-0.1)
  rect 1.4x0.4 smd: N(0,0.8) O(0,-0.8)
QFN40P800X800_68-H580N
  rect 0.8x0.2 smd: 1(-3.95,3.2) 2(-3.95,2.8) 3(-3.95,2.4) 4(-3.95,2) 5(-3.95,1.6) 6(-3.95,1.2) 7(-3.95,0.8) 8(-3.95,0.4) 9(-3.95,0) 10(-3.95,-0.4) 11(-3.95,-0.8) 12(-3.95,-1.2) 13(-3.95,-1.6) 14(-3.95,-2) 15(-3.95,-2.4) 16(-3.95,-2.8) 17(-3.95,-3.2) 35(3.95,-3.2) 36(3.95,-2.8) 37(3.95,-2.4) 38(3.95,-2) 39(3.95,-1.6) 40(3.95,-1.2) 41(3.95,-0.8) 42(3.95,-0.4) 43(3.95,0) 44(3.95,0.4) 45(3.95,0.8) 46(3.95,1.2) 47(3.95,1.6) 48(3.95,2) 49(3.95,2.4) 50(3.95,2.8) 51(3.95,3.2)
  rect 0.2x0.8 smd: 18(-3.2,-3.95) 19(-2.8,-3.95) 20(-2.4,-3.95) 21(-2,-3.95) 22(-1.6,-3.95) 23(-1.2,-3.95) 24(-0.8,-3.95) 25(-0.4,-3.95) 26(0,-3.95) 27(0.4,-3.95) 28(0.8,-3.95) 29(1.2,-3.95) 30(1.6,-3.95) 31(2,-3.95) 32(2.4,-3.95) 33(2.8,-3.95) 34(3.2,-3.95) 52(3.2,3.95) 53(2.8,3.95) 54(2.4,3.95) 55(2,3.95) 56(1.6,3.95) 57(1.2,3.95) 58(0.8,3.95) 59(0.4,3.95) 60(0,3.95) 61(-0.4,3.95) 62(-0.8,3.95) 63(-1.2,3.95) 64(-1.6,3.95) 65(-2,3.95) 66(-2.4,3.95) 67(-2.8,3.95) 68(-3.2,3.95)
  rect 5.8x5.8 smd: H(0,0)
QFN50P300X300X100-17N_TI
  rrect 0.6x0.24 smd: 1(-1.4,0.75) 2(-1.4,0.25) 3(-1.4,-0.25) 4(-1.4,-0.75) 9(1.4,-0.75) 10(1.4,-0.25) 11(1.4,0.25) 12(1.4,0.75)
  rrect 0.24x0.6 smd: 5(-0.75,-1.4) 6(-0.25,-1.4) 7(0.25,-1.4) 8(0.75,-1.4) 13(0.75,1.4) 14(0.25,1.4) 15(-0.25,1.4) 16(-0.75,1.4)
  rrect 1.68x1.68 smd: H(0,0)
RESC0603_0201N
  rect 0.25x0.35 smd: 1(-0.3,0) 2(0.3,0)
RESC1005_0402N
  rect 0.4x0.55 smd: 1(-0.425,0) 2(0.425,0)
RESC1608_0603N
  rect 0.9x1 smd: 1(-0.75,0) 2(0.75,0)
SAMT_FTSH-105-XX-X-DV-K
  rect 0.75x2.8 smd: 1(-2.54,-2.03) 2(-2.54,2.03) 3(-1.27,-2.03) 4(-1.27,2.03) 5(0,-2.03) 6(0,2.03) 7(1.27,-2.03) 8(1.27,2.03) 9(2.54,-2.03) 10(2.54,2.03)
SOD2512X110N
  rect 0.8x0.6 smd: A(1.25,0) K(-1.25,0)
SODFL1608X77N
  rect 0.6x0.8 smd: A(-0.85,0) K(0.85,0)
SON127P800X600_8-H410X350
  rect 0.95x0.45 smd: 1(-3.9,1.905) 2(-3.9,0.635) 3(-3.9,-0.635) 4(-3.9,-1.905) 5(3.9,-1.905) 6(3.9,-0.635) 7(3.9,0.635) 8(3.9,1.905)
  rect 3.55x4.15 smd: H(0,0)
SOTFL40P120X59-3N
  rect 0.45x0.4 smd: 1(-0.525,0.4) 2(-0.525,-0.4) 3(0.525,0)
SULLINS_PRPC006SFAN-RC
  rect 1.6x1.6 hole 1: 1(0,0)
  round 1.6 hole 1: 2(2.54,0) 3(5.08,0) 4(7.62,0) 5(10.16,0) 6(12.7,0)
SULLINS_PRPC009SFAN-RC
  rect 1.6x1.6 hole 1: 1(0,0)
  round 1.6 hole 1: 2(2.54,0) 3(5.08,0) 4(7.62,0) 5(10.16,0) 6(12.7,0) 7(15.24,0) 8(17.78,0) 9(20.32,0)
SW_435171014816
  rect 0.65x0.6 smd: 1(-1.575,0.85) 2(1.575,0.85) 3(-1.575,-0.85) 4(1.575,-0.85)
  rect 0.35x0.7 smd: 5(-1.725,0) 6(1.725,0)
TP102C
  round 1.016 smd: 1(0,0)
unnamed#2
  round 1 hole 3 unplated: (0,0)
VF2BGA40N50P9X12_500X650X90
  round 0.275 smd: A1(-2.17,2.58) A2(-1.67,2.58) A3(-1.17,2.58) A4(-0.67,2.58) A5(-0.17,2.58) A6(0.33,2.58) A7(0.83,2.58) A8(1.33,2.58) A9(1.83,2.58) B1(-2.17,2.08) B3(-1.17,2.08) B4(-0.67,2.08) B8(1.33,2.08) B9(1.83,2.08) C1(-2.17,1.58) C9(1.83,1.58) D1(-2.17,1.08) D9(1.83,1.08) E1(-2.17,0.58) E9(1.83,0.58) F1(-2.17,0.08) F9(1.83,0.08) G1(-2.17,-0.42) G9(1.83,-0.42) H1(-2.17,-0.92) H9(1.83,-0.92) J1(-2.17,-1.42) J9(1.83,-1.42) K1(-2.17,-1.92) K9(1.83,-1.92) L1(-2.17,-2.42) L9(1.83,-2.42) M1(-2.17,-2.92) M2(-1.67,-2.92) M3(-1.17,-2.92) M4(-0.67,-2.92) M5(-0.17,-2.92) M6(0.33,-2.92) M7(0.83,-2.92) M9(1.83,-2.92)
XTAL_ABS05_1M6X1M
  rect 0.5x1 smd: 1(-0.6,0) 2(0.6,0)

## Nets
GND_EARTH: C6.1 J1.SH1 J1.SH2 J1.SH3 J1.SH4 J2.SH1 J2.SH2 J2.SH3 J2.SH4 R7.1
GND_SIGNAL: A2.2 A2.3(GND#3) C1.2 C2.2 C3.2 C4.2 C5.2 C6.2 C7.2 C8.2 C9.2 C10.2 C11.2 C12.2 C13.2 C14.2 C15.2 C16.2 C17.2 C18.2 C19.2 C20.2 C21.2 C22.2 C23.2 C24.2 C25.2 C26.2 C27.2 C28.2 C29.2 C30.2 C31.2 C32.2 C33.2 C34.2 C35.2 C36.2 C37.2 C38.2 C39.2 C40.2 C41.2 C42.2 C43.2 C44.2 C45.2 C46.2 C47.2 C48.2 C49.2 C50.2 C51.2 C52.2 C53.2 C54.2 C55.2 C56.2 C57.2 C58.2 C60.1 C61.1 C62.2 C63.2 C66.2 C67.2 C68.2 C71.2 C72.2 C73.2 C74.2 C75.2 C76.2 C77.2 C78.2 C79.2 C80.1 C81.2 C82.2 C83.2 C84.2 C85.2 C86.2 C87.2 C88.2 C89.2 C92.2 C93.2 C99.2 C115.2 C116.1 C119.2 C121.2 C245.2 C247.2 C248.2 C249.2 C250.2 C256.2 D1.K(CATHODE) D2.K(CATHODE) D3.K(CATHODE) D4.A D9.A D10.A D12.K(CATHODE) J1.A1 J1.A12 J1.B1 J1.B12 J2.A1 J2.A12 J2.B1 J2.B12 J3.2 J3.SH1 J3.SH2 J4.3 J4.5 J4.7 J4.9 J5.G1 J5.G2 J5.G3 J15.19 J15.20 J15.SH1 J15.SH2 J15.SH3 J15.SH4 J16.1 J16.SH1 J16.SH2 J17.6 J18.9 L4.2 R5.2 R6.2 R7.2 R8.1 R9.1 R10.1 R11.1 R12.1 R14.2 R15.2 R16.2 R17.2 R18.2 R23.2 R24.2 R29.1 R31.1 R36.1 R55.1 R66.2 R74.2 R82.2 R101.2 R102.2 R280.1 R287.2 SW1.3 SW1.4 SW1.5 SW1.6(GND#6) SW2.5 SW2.6(GND#6) SW3.3 SW3.4 SW3.5 SW3.6(GND#6) TP2.1(TP) TP4.1(TP) TP6.1(TP) U1.B12 U1.C3 U1.D4 U1.D10 U1.K4 U1.K10(VSS5) U2.5 U2.7 U2.8 U2.9 U2.25 U2.43 U2.45 U2.58 U2.62 U2.63 U2.H U3.1 U3.7 U4.5 U5.5 U6.A1 U6.A2 U6.A3 U6.A4 U6.A5 U6.A6 U6.A7 U6.A8 U6.A9 U6.B3 U6.B4 U6.B8 U6.B9 U6.C9(VSSRF_9) U6.D9 U6.E9 U6.H9 U6.J9 U6.K1 U6.K9 U6.L9 U6.M7 U6.M9 U7.4(VSS) U7.H U8.8(VSS) U8.H U9.3 U11.3 U11.9 U11.H U15.2 U16.3 U17.1 U17.12 U17.19 U17.21 U17.29 U17.32 U17.33 U17.35 U17.40 U17.42 U17.43 U17.44 U17.45 U17.46 U18.6 U18.7 U19.B1 U19.C3 U20.2 U20.5 U21.2 U21.5 Y2.2 Y2.4(GND_2) Y3.G
VBAT: C247.1 R96.2 TP23.1(TP) U17.30
VBAT_IN: C5.1 J3.1 TP34.1(TP) U8.2 U8.3
VBUS_IN: C3.1 C4.1 D5.K D6.K R3.2 R4.2 R13.2 TP30.1(TP) U8.13
VCC_1V8: C15.1 C72.1 C74.1 C76.1 C78.1 C87.1 C92.1 C93.1 C119.1 FB6.1 FB7.1 FB8.1 FB9.1 FB11.1 FB12.1 J15.2 R84.1 R85.1 R97.1 R277.1 R278.1 U7.8 U19.C1 U21.1(OUT)
VCC_3V3: C12.1 C66.1 C67.1 C68.1 C71.1 C81.1 C115.1 C116.2 C121.1 FB10.1 J15.1 J16.2 J17.5 R39.1 R73.1 R81.1 R285.2 R286.2 TP10.1(TP) U3.6(VDDIO) U3.8 U4.2(VDD) U5.2(VDD) U18.5(VDDIO) U18.8 U19.B2 U19.B3(VDDIO) U20.1(OUT)
VCC_3V6: C7.1 C8.1 C10.1 C11.1 C13.1 C14.1 C253.1 C256.1 R19.1 R21.1 R25.1 R26.1 R96.1 TP32.1(TP) U11.1(VOUT) U20.4 U21.4
VCCD: C39.1 R40.2 TP12.1(TP) U1.A2
VDD_NS: C36.1 C55.1 FB3.1 U1.J1
VDDA: C40.1 C47.1 C48.1 C49.1 FB5.1 U1.A12 U1.A13
VDDA_RADAR: C75.1 FB7.2 U6.J1
VDDD: C38.1 C50.1 C51.1 C52.1 FB4.1 R41.1 R275.1 R284.1 U1.A1 U1.K12
VDDD_RADAR: C73.1 FB6.2 U6.H1
VDDIO0: C53.1 C54.1 R277.2 U1.C4
VDDIO2: C45.1 C46.1 R278.2 U1.L4
VDDIO_1YN: C99.1 C249.1 R42.1 R43.1 R44.1 R45.1 R46.1 R47.1 R50.1 R58.1 R97.2 TP24.1(TP) U17.36 Y3.P(VDD)
VDDLF_RADAR: C82.1 FB10.2 U6.M3
VDDPLL_RADAR: C79.1 FB9.2 U6.M4
VDDRF_RADAR: C83.1 C84.1 C85.1 C86.1 FB11.2 U6.F9 U6.G9 U6.M1
VDDUSB: C41.1 C42.1 R275.2 U1.M1
VDDVCO_RADAR: C77.1 FB8.2 U6.M6
VIN: C9.1 R20.1 R22.1 R290.1 TP33.1(TP) U11.5 U11.8
ANT0: C254.1 C255.2 U17.41
ANT1: C246.1 C250.1 C254.2
ANT2: C255.1 J5.S(SIG)
BT_DEV_WAKE: U1.N6 U17.39
BT_HOST_WAKE: U1.L7 U17.38
BT_REG_ON: R58.2 U1.M6 U17.14
BT_UART_CTS: R59.1 U17.4
BT_UART_RTS: R60.1 U17.5
BT_UART_RXD: R57.1 U17.2
BT_UART_TXD: R56.1 U17.3
ECO_XTAL_IN_P12_6: C62.1 U1.A4 Y2.1
ECO_XTAL_OUT_P12_7: C63.1 U1.B4 Y2.3
EXT_LPO: R100.2 U17.37
I2C_SCL_P0_2: J16.4 J17.4 R64.2 R282.1 R296.2 U1.E1 U18.13 U19.A3
I2C_SDA_P0_3: J16.3 J17.3 R65.2 R281.1 R295.2 U1.F3 U18.14 U19.A2
IMU_INT1_P1_5: U1.J3 U18.4
IMU_INT2_P0_4: U1.F2 U18.9
KP_UART_RX_P5_1: R34.1 R289.1 U2.21
KP_UART_TX_P5_0: R288.1 U2.20
KP_USB_DM: J1.A7 J1.B7 R37.1 U16.1
KP_USB_DP: J1.A6 J1.B6 R35.1 U16.2(IN2)
KP_VBUS: D5.A D10.K(CATHODE) J1.A4 J1.A9 J1.B4 J1.B9(VBUS_4) R27.2 R101.1 TP1.1(TP)
LBCPP_CE_N_P5_7: R10.2 U1.N10 U8.4
LBCPP_CHG_N_P5_6: R298.1 U1.N9
LBCPP_EN1_P6_1: R3.1 R11.2 U1.L10 U8.6
LBCPP_EN2_P6_0: R4.1 R12.2 U1.M10 U8.5
LBCPP_ITERM_P6_3: R283.2 U1.M11
LBCPP_PG_N_P5_5: R297.1 U1.M9
MAG_INT_P1_0: U1.G2 U19.A1
P5LP1_2: SW3.1 SW3.2 U2.13
P5LP1_4: R38.2 U2.15
P5LP2_2: U2.64
P5LP2_3: U2.65
P5LP2_4: U2.66
P5LP_SIO_VREF: R28.2 R29.2 U2.48
P5LP_SWCLK: TP8.1(TP) U2.12
P5LP_SWDIO: TP9.1(TP) U2.11
P5LP_VCCD: C25.1 C26.1 U2.26 U2.57
P5LP_VDD: C16.1 C17.1 C18.1 C19.1 C20.1 C21.1 C22.1 C23.1 C27.1 C28.1 C29.1 C30.1 C31.1 C32.1 R27.1 R33.1 TP5.1(TP) U2.17 U2.24 U2.35 U2.44 U2.52 U2.59 U2.67
P5LP_XRES: TP7.1(TP) U2.10(X\R\E\S\)
P6_RESET_L: C57.1 J4.10 R41.2 SW1.1 SW1.2 U1.F1 U2.3
P6_SWCLK_P6_7: J4.4 U1.M13 U2.47
P6_SWDIO_P6_6: J4.2 U1.N12 U2.46
P6_SWO_P6_4: J4.6 U1.N11
P6_TDI_P6_5: J4.8 U1.M12
P6_USB_DM: J2.A7 J2.B7 U1.L1 U9.1
P6_USB_DP: J2.A6 J2.B6 U1.L2 U9.2(IN2)
P6_USB_S_P6_2: R279.2 R280.2 U1.L11
P6_VBUS: D4.K(CATHODE) D6.A J2.A4 J2.A9 J2.B4 J2.B9(VBUS_4) R102.1 R279.1 TP3.1(TP)
P6_VTARG: C56.1 D9.K(CATHODE) FB3.2 FB4.2 FB5.2 J4.1 R28.1 R30.1 R34.2 R39.2 R281.2 R282.2 TP11.1(TP)
P8_0: J15.7 U1.H13
P8_1: J15.5 U1.H12
P8_2: J15.3 U1.H11
P8_3: J15.9 U1.G13
P8_4: J15.11 U1.G12
P8_5: J15.13 U1.G11
P9_0: J18.1 U1.E11
P9_1: J18.2 U1.E12
P9_2: J18.3 U1.E13
P9_3: J18.4 U1.F11
P9_4: J18.5 U1.D13
P9_5: J18.6 U1.D12
P9_6: J18.7 U1.D11
P9_7: J18.8 U1.C13
P10_0_UART_RX: J17.1 U1.C12
P10_1_UART_TX: J17.2 U1.A11
PDM_CLK_P10_4: R72.2 R80.2 U1.A10
PDM_DATA_P10_5: R71.2 R79.2 U1.B10
PSEN_INT_P1_4: R66.1 U1.H1 U3.5
QSPI_CLK_P11_7: R87.2 U1.C7
QSPI_DATA0_P11_6: R88.2 U1.B7
QSPI_DATA1_P11_5: R89.2 U1.A7
QSPI_DATA2_P11_4: R90.2 U1.C8
QSPI_DATA3_P11_3: R91.2 U1.B8
QSPI_SEL_L_P11_2: R86.2 U1.A8
ROSC_IN_80MHZ: R83.2 U6.M2
RSPI_CLK_P12_2: R292.1 U1.C6
RSPI_CS_P12_3: R291.1 U1.A5
RSPI_IRQ_P11_0: U1.B9 U6.C1
RSPI_MISO_P12_1: R294.1 U1.B6
RSPI_MOSI_P12_0: R293.1 U1.A6
RXRES_L_P11_1: R299.1 U1.C9
SDHC_CLK: J15.15 U1.C5
SDHC_CMD: J15.17 U1.B5
SDHC_DATA00: J15.18 U1.B1
SDHC_DATA01: J15.16 U1.A3
SDHC_DATA02: J15.14 U1.B3
SDHC_DATA03: J15.12 U1.B2
SDHC_DATA10: J15.10 U1.C2
SDHC_DATA11: J15.8 U1.C1
SDHC_DATA12: J15.6 U1.D3
SDHC_DATA13: J15.4 U1.D2
SDIO_CLK: R46.2 R54.1 U17.20
SDIO_CMD: R45.2 R53.1 U17.22
SDIO_DATA0: R42.2 R48.1 U17.24
SDIO_DATA1: R49.1 R50.2 U17.26
SDIO_DATA2: R43.2 R51.1 U17.23
SDIO_DATA3: R44.2 R52.1 U17.25
USB_V_SENSE: R33.2 R36.2 U2.19
USER_BTN_P5_2: C58.1 SW2.1 SW2.2 U1.M8
USER_LED1_P5_3: R62.2 U1.N8
USER_LED2_P5_4: R63.2 U1.L9
VBACKUP: C43.1 C44.1 R284.2 U1.D1
VBUCK: C35.1 L2.2 R40.1
VREF: C37.1 U1.B13
VTARG_MEAS: R30.2 R31.2 U2.32
WCO_XTAL_IN_P0_0: C60.2 U1.E3 Y1.2
WCO_XTAL_OUT_P0_1: C61.2 U1.E2 Y1.1
WL_HOST_WAKE: U1.M7 U17.27
WL_REG_ON: R47.2 U1.M4 U17.28(WL_REG_ON)
N17065875: L2.1 U1.J2
N17073640: R48.2 U1.M2
N17073643: R49.2 U1.N2
N17073646: R51.2 U1.L3
N17073649: R52.2 U1.M3
N17073652: R53.2 U1.N3
N17073655: R54.2 U1.N1
N17076511: R56.2 U1.L5
N17076512: R57.2 U1.M5
N17076513: R60.2 U1.L6
N17076514: R59.2 U1.N5
N17278110: R19.2 U20.3
N17278725: R64.1 U3.4
N17278748: R65.1 U3.3
N17279219: R73.2 R74.1 U4.4
N17279342: R81.2 R82.1 U5.4
N17289581: R88.1 U7.5
N17289597: R89.1 U7.2
N17289613: R90.1 U7.3
N17289629: R91.1 U7.7
N17305257: C248.1 L3.1 U17.31
N17305261: L3.2 U17.34
N17332525: A2.1 A2.4 C246.2 L4.1
N17332695: TP17.1(TP) U17.18
N17332709: TP19.1(TP) U17.17
N17332795: TP28.1(TP) U17.10
N17363073: J1.A5 R6.1
N17363075: J1.B5 R5.1
N17373677: J2.A5 R18.1
N17373681: J2.B5 R17.1
N17374662: D8.K(CATHODE) R297.2 U8.7
N17374666: D8.A R1.1
N17374668: C1.1 C2.1 R1.2 R2.2 R290.2 U8.10 U8.11
N17374688: D11.K(CATHODE) R298.2 U8.9
N17374692: D11.A R2.1
N17374847: R8.2 U8.1
N17374885: R9.2 U8.14
N17374979: R13.1 R14.1 R283.1 U8.15
N17374981: R15.1 U8.12
N17374983: R16.1 U8.16
N17378355: C253.2 R21.2 R23.1 U11.10
N17378650: D1.A R26.2
N17390542: R25.2 U21.3
N17393871: L1.1 U11.2
N17393876: L1.2 U11.4
N17394939: R20.2 U11.6
N17395527: R22.2 R24.1 U11.7
N17444411: C245.1 U19.C2
N17459450: R100.1 Y3.O
N17461053: TP16.1(TP) U6.M5
N17461288: C80.2 U6.L1
N17462113: C88.1 C89.1 FB12.2 U15.4(VCC)
N17462137: R83.1 U15.3
N17489317: R55.2 SW2.3 SW2.4
N17489457: D2.A R62.1
N17489487: D3.A R63.1
N17505741: TP29.1(TP) U17.8
N17505744: TP27.1(TP) U17.9
N17505747: TP26.1(TP) U17.11
N17506574: R285.1 U18.12
N17506591: R286.1 R287.1 U18.1
N17531797: R84.2 R86.1 U7.1
N17531826: R85.2 R87.1 U7.6
N17580471: C24.1 U2.53
N17581080: C33.1 U2.42
N17581130: R35.2 U2.22
N17581131: R37.2 U2.23
N17581135: C34.1 U2.31
N17592490: R288.2 U1.N7
N17592497: R289.2 U1.L8
N17595841: R294.2 U6.E1
N17595844: R293.2 U6.D1
N17595847: R292.2 U6.B1
N17595850: R291.2 U6.G1
N17595911: R295.1 U2.39
N17595914: R296.1 U2.38
N17604769: R299.2 U6.F1
N17606878: D12.A R38.1
N17607574: TP31.1(TP) U1.G3
N172791730: R71.1 U4.1
N172792960: R79.1 U5.1
N173838130: R72.1 U4.3
N173838340: R80.1 U5.3

Pads without a net: J1 A8 B8; J2 A8 B8; U1 A9 B11 C10 C11 F12 F13 G1 H2 H3 J11 J12 J13 K1 K2 K3 K11 K13 L12 L13 N4 N13; U2 1 2 4 6 14 16 18 27 28 29 30 33 34 36 37 40 41 49 50 51 54 55 56 60 61 68; U3 2; U15 1; U17 6 7 13 15 16; U18 2 3 10 11; Y3 N

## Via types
v1: diameter 0.406, hole 0.203, TOP to BOTTOM, 573 vias

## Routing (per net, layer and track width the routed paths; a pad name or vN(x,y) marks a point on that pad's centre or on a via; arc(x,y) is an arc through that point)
GND_EARTH: length 24.4
  BOTTOM w0.305: 5.4,3.05 J2.SH3 6.11,1.94 ; J1.SH2 29.36,7.38 ; J1.SH2 30.06,6.12 ; J1.SH2 29.36,4.87 ; J1.SH2 28.65,6.12 ; J2.SH4 14.75,1.94 ; J2.SH4 13.34,1.94 ; J2.SH4 14.04,3.05 ; J1.SH3 20.72,3.05 ; J1.SH3 21.42,1.94 ; J1.SH3 20.01,1.94 ; 29.36,3.05 J1.SH4 28.65,1.94 ; 14.04,4.87 J2.SH2 ; J2.SH2 14.04,7.38 ; J2.SH2 14.75,6.12 ; J2.SH2 13.34,6.12 ; 20.72,4.87 J1.SH1 ; J1.SH1 21.42,6.12 ; J1.SH1 20.01,6.12 ; J1.SH1 20.72,7.38 ; J2.SH1 5.4,7.38 ; J2.SH1 5.4,4.87 ; J2.SH1 4.69,6.12 ; J2.SH1 6.11,6.12
GND_SIGNAL: length 211.4
  TOP w0.229: C81.2 16,15.4 15.78,15.19 v1(15.78,14.4) ; C67.2 6.79,20.25 6.57,20.47 6.57,20.48 6.5,20.56 U3.7 ; 3.68,41.42 3.68,41.15 3.84,40.98 v1(3.84,40.87) ; C58.2 19.43,24.41 R55.1 19.43,23.22 19.6,23.06 20.16,23.06 20.67,23.57 20.89,23.57 v1(21.31,23.57) ; 20.68,13.94 21.13,14.39 U6.M9 U6.M7 ; U6.B8 26.53,15.16 26.76,15.39 U6.A7 28.72,15.39 ; U19.C3 17.4,21.97 17.26,22.12 C115.2 ; C78.2 v1(17.95,10.12) ; v1(25,41.53) 24.95,41.48 Y3.G ; SW1.3 27.96,25.37 v1(27.57,25.37) SW1.5 ; SW2.5 22.84,26.14 v1(23.17,26.47) 22.84,26.8 SW2.6 ; U3.1 5.85,21.61 5.38,21.15 5.38,20.31 5.54,20.15 C66.2 v1(4.81,19.86) ; C87.2 21.17,12.53 21.17,12.88 20.68,13.36 20.68,13.41 ; v1(11.47,19.63) 11.47,19.93 C121.2 11.66,20.66 11.39,20.93 U18.7 ; 20.02,21.72 20.18,21.56 20.81,21.56 20.94,21.69 v1(21.41,21.69) ; C76.2 v1(16.21,8.86) ; v1(25.79,39.01) 25.71,39.09 C249.2 ; U1.K4 v1(12.63,27.36) ; C119.2 19.62,21.74 19.18,21.74 19.01,21.57 U19.B1 ; C73.2 25.43,20.44 25.69,20.7 v1(26.05,20.7) ; U1.C3 v1(8.09,26.73) ; U17.1 v1(20.35,35.54) ; v1(22.82,19.76) 23.07,20.02 23.07,20.19 C75.2 ; U17.19 24.09,31.92 v1(23.72,32.29) ; v1(27.59,23.04) 27.59,22.54 C72.2 26.72,22.43 C74.2 ; v1(9.48,44.53) 9.96,44.05 J4.5 ; 23.5,13.36 22.84,13.36 22.53,13.67 U6.K9 U6.L9 ; U6.A9 28.57,14.39 ; R101.2 3.67,5.85 v1(3.95,6.12) 3.57,6.5 R102.2 ; U17.29 23.82,34.19 v1(23.72,34.29) 24.09,34.67 U17.35 ; U15.2 18.11,16.71 18.34,16.94 v1(18.34,16.94) ; C84.2 18.3,18.44 18.07,18.67 v1(18.04,18.67) ; U6.B9 26.53,13.67 ; J4.7 8.69,44.13 v1(8.28,44.54) 7.42,43.68 J4.9 ; U6.K1 22.53,19.12 ; v1(22.85,21.71) 22.75,21.62 C80.1 ; J4.3 v1(11.23,44.53) ; U17.33 v1(25.61,36.22) ; U18.6 10.89,20.61 10.96,20.55 C116.1 v1(10.96,19.64) ; v1(27.75,35.23) 27.75,34.65 C248.2 ; SW1.6 27.57,27.64 27.84,27.37 v1(28.42,27.37) SW1.4 ; U1.B12 v1(7.44,33.23) ; U17.40 v1(21.84,37.21) ; U6.A3 27.51,17.39 ; 27.49,18.26 27.37,18.39 U6.A1 ; 27.62,16.48 27.22,16.89 U6.A4 ; U17.12 20.64,30.37 20.51,30.51 v1(20.33,30.51) ; v1(18.68,11.96) 18.68,11.86 19.05,11.49 C77.2 ; U1.K10 v1(13.29,31.93) ; D2.K 14.87,20.84 15.79,21.76 15.79,22.69 v1(15.46,23.02) ; U6.A6 28.27,15.89 ; C99.2 v1(25.99,37.8) ; U6.H9 23.5,14.36 23.5,13.87 ; v1(25.08,9.04) 25.08,9.84 D1.K ; 18.97,16.21 18.97,16.21 19.06,16.12 C82.2 ; U17.32 25.44,35.54 25.61,35.71 v1(25.61,35.71) ; U17.42 v1(20.88,37.21) ; U17.21 v1(25.55,30.37) ; U6.D9 25.53,13.92 ; U1.D10 v1(8.74,31.93) ; U1.D4 v1(8.74,27.38)
  TOP w0.305: J17.6 2.84,33.58 ; J17.6 1.84,32.57 ; J17.6 1.84,34.59 ; 31.85,33.35 J18.9 ; J18.9 32.85,34.36 ; J18.9 32.85,32.35
  L02_GND1 w0.089: 8.44,33.55 7.77,33.55 v1(7.44,33.23) 7.12,33.55 6.39,33.55
  L02_GND1 w0.305: J17.6 1.84,34.59 ; J17.6 1.84,32.57 ; J17.6 2.84,33.58 ; J18.9 32.85,34.36 ; J18.9 31.85,33.35 ; J18.9 32.85,32.35
  L03_SIG1 w0.305: 32.85,32.35 J18.9 ; J18.9 32.85,34.36 ; J18.9 31.85,33.35 ; 1.84,32.57 J17.6 ; J17.6 2.84,33.58 ; J17.6 1.84,34.59
  L04_SIG2 w0.305: J18.9 32.85,34.36 ; J18.9 31.85,33.35 ; J18.9 32.85,32.35 ; J17.6 1.84,34.59 ; J17.6 1.84,32.57 ; J17.6 2.84,33.58
  L05_GND2 w0.089: 8.46,33.55 7.77,33.55 v1(7.44,33.23) 7.12,33.55 6.41,33.55
  L05_GND2 w0.305: 31.85,33.35 J18.9 ; J18.9 32.85,32.35 ; J18.9 32.85,34.36 ; J17.6 1.84,34.59 ; J17.6 1.84,32.57 ; J17.6 2.84,33.58
  BOTTOM w0.15: C62.2 8.83,32.02 v1(8.74,31.93) ; v1(13.29,31.93) 13.02,31.66 Y2.2 ; C60.1 v1(10.68,27.75) ; C63.2 10.02,31.09 v1(10.18,31.09) 10.71,30.56 Y2.4
  BOTTOM w0.203: C45.2 12.88,27.61 v1(12.63,27.36)
  BOTTOM w0.229: v1(18.25,34.87) 18.56,35.19 U7.4 ; C17.2 23.15,16.8 23.25,16.89 23.25,17.76 U2.25 23.25,19.33 v1(22.82,19.76) ; C51.2 5.74,24.12 5.87,23.99 C38.2 v1(5.19,23.4) ; v1(20.96,44.35) 21.53,44.35 21.87,44.01 J16.SH2 ; v1(21.35,27.86) 21.83,27.86 22.25,27.44 C26.2 22.26,27.15 22.26,26.77 22.05,26.56 U2.58 22.05,24.34 v1(22.82,23.57) 23.65,24.4 U2.62 23.65,26.62 23.53,26.74 C32.2 ; C33.2 16.88,21.22 ; D4.A 11.21,4.75 ; R10.1 2.91,15.04 2.57,15.04 ; v1(24.72,21.67) 24.72,22 25.24,22.51 U2.7 ; v1(15.1,43.81) 15.25,43.66 J16.SH1 ; C44.2 C43.2 8.4,24.31 7.97,23.88 v1(7.53,23.88) ; v1(24.72,19.76) 24.85,19.89 24.85,20.85 25.51,21.51 25.51,22.02 25.6,22.11 U2.8 ; R18.2 8.37,5.82 8.27,5.72 ; C30.2 C29.2 20.04,28.14 v1(20.08,28.11) 20.08,28.04 20.32,27.8 C24.2 ; U2.45 22.05,22.51 v1(22.85,21.71) 24.05,22.91 ; R11.1 6.51,16.48 6.51,16.48 6.52,16.48 ; v1(14.42,21.89) 14.37,21.84 C35.2 ; R6.2 23.69,5.91 23.54,5.75 ; C41.2 15.41,24.47 15.41,24.47 C42.2 15.41,23.66 15.45,23.62 15.45,23.03 v1(15.46,23.02) ; C89.2 15.02,15.23 v1(15.02,14.68) ; C71.2 v1(30.26,40.82) ; C37.2 7.02,34.7 v1(7.25,34.92) ; v1(28.23,14.94) 27.79,15.38 R36.1 ; v1(6.28,21.82) 6.3,21.8 R287.2 ; 11.48,5.73 11.07,6.13 R17.2 ; v1(6.14,37.59) D9.A 6.31,38.55 6.31,38.79 6.47,38.95 7.05,38.95 7.28,39.18 C56.2 ; C19.2 C18.2 16.27,19.2 16.21,19.25 v1(16.14,19.25) ; C61.1 12.54,27.28 v1(12.63,27.36) ; v1(23.86,29.06) 23.86,28.31 C31.2 ; R5.2 26.4,6.07 26.73,5.74 ; C49.2 C48.2 5.43,31.94 5.43,31.51 5.09,31.17 v1(5.08,31.17) ; 27.51,23.62 27.2,23.31 U2.5 25.38,23.31 24.98,22.91 24.05,22.91 ; U16.3 25.79,6 26.04,5.74 ; v1(26.05,20.7) 26.05,21.48 26.28,21.71 U2.9 ; C52.2 v1(12.62,34.93) ; U2.63 24.05,22.91 ; v1(26.34,26.56) C28.2 26.33,27.14 C27.2 ; v1(8.74,27.38) 8.84,27.38 9.17,27.7 C53.2 ; v1(21.41,21.69) 20.89,21.69 20.87,21.71 U2.43 17.8,21.71 17.69,21.6 17.45,21.6 C21.2 ; R16.2 4.76,10.24 4.89,10.11 v1(4.89,9.8) ; C36.2 11.09,24.5 ; v1(29.48,30.6) C93.2 C92.2 ; SW3.3 28.49,9.88 ; 26.65,4.73 D10.A ; R12.1 3.16,16.48 ; v1(28.78,16.65) C22.2 C23.2 ; v1(10.75,5.71) 10.54,5.93 10.18,5.93 10.12,5.98 U9.3 ; C40.2 v1(6.02,29.7) ; C25.2 21.88,15.9 21.72,15.74 21.08,15.74 C34.2 21.06,15.73 R31.1 19.4,14.87 18.94,14.87 ; v1(15.78,14.4) 15.78,14.75 C88.2 ; v1(5.74,26.64) C39.2
  BOTTOM w0.254: U5.5 v1(32.28,42.61) ; 30.78,41.81 30.78,41.28 ; 3.96,43.38 3.96,44 ; U4.5 v1(2.46,42.61) ; 30.81,43.38 30.81,44.02 ; 3.96,41.81 3.96,41.25
  BOTTOM w0.305: J17.6 1.84,34.59 ; J17.6 1.84,32.57 ; J17.6 2.84,33.58 ; 32.85,32.35 J18.9 ; J18.9 31.85,33.35 ; J18.9 32.85,34.36
  vias: v1(1.32,16.19) v1(1.32,15.14) v1(1.31,14.04) v1(1.3,13.07) v1(1.26,12.12) v1(1.45,19.42) v1(1.45,18.83) v1(1.53,35.14) v1(1.72,43.58) v1(1.7,42.67) v1(1.7,41.7) v1(2.32,44.39) v1(2.35,35.05) v1(2.5,41.73) v1(2.68,43.79) v1(2.97,41.03) v1(3.67,44.25) v1(4.57,44.26) v1(4.63,40.41) v1(6.79,19.31) v1(8.18,17.65) v1(8.62,19.28) v1(8.92,8.2) v1(9.36,40.41) v1(9.68,16.08) v1(9.91,16.59) v1(10.52,8.2) v1(10.6,24.51) v1(10.65,44.53) v1(10.82,18.03) v1(11.12,17.5) v1(11.72,9.63) v1(12.13,44.53) v1(12.3,9.63) v1(13.42,44.5) v1(13.57,39.83) v1(14.16,16.35) v1(14.3,37.57) v1(14.44,44.42) v1(14.44,43.84) v1(15.12,44.42) v1(15.07,43.15) v1(15.15,41) v1(15.12,8.56) v1(15.55,40.41) v1(15.81,8.36) v1(16,6.71) v1(16.09,40.03) v1(16.05,5.68) v1(16.19,40.84) v1(16.26,7.85) v1(16.42,21.11) v1(16.65,40.41) v1(16.71,7.37) v1(16.77,39.85) v1(16.87,39.32) v1(17.09,5.82) v1(17.47,22.58) v1(18.09,40.94) v1(18.17,44.35) v1(18.42,43.84) v1(18.73,44.35) v1(18.73,40.94) v1(18.75,7.92) v1(18.94,5.88) v1(19.01,43.84) v1(19.01,3.41) v1(19.29,44.35) v1(19.26,43.26) v1(19.26,42.67) v1(19.26,42.11) v1(19.26,40.94) v1(19.59,43.84) v1(19.85,44.35) v1(19.82,40.94) v1(19.87,42.67) v1(19.87,42.14) v1(20.41,44.35) v1(20.68,42.75) v1(20.66,42.16) v1(21.5,20.42) v1(22.03,40.59) v1(22.03,39.95) v1(22.03,39.34) v1(22.08,42.44) v1(22.22,34.29) v1(22.22,33.3) v1(22.22,32.29) v1(22.44,41.53) v1(22.46,42.06) v1(22.69,40.54) v1(22.69,39.95) v1(22.67,39.37) v1(22.95,41.53) v1(23.3,40.54) v1(23.25,40.03) v1(23.45,41.53) v1(23.45,39.37) v1(23.72,33.3) v1(23.96,41.53) v1(24.32,8.18) v1(24.47,41.53) v1(24.72,23.57) v1(25.54,41.53) v1(25.79,8.18) v1(26.07,41.53) v1(26.6,41.53) v1(26.96,40.97) v1(27.14,41.53) v1(27.33,31.91) v1(27.49,41.02) v1(27.67,41.53) v1(27.9,44.17) v1(27.9,43.61) v1(27.9,43.08) v1(27.9,42.55) v1(27.9,42.01) v1(28.33,44.5) v1(28.84,8.92) v1(29.3,44.48) v1(29.6,8.89) v1(30.38,44.49) v1(30.38,8.82) v1(30.39,5.21) v1(31.1,44.5) v1(31.1,40.77) v1(31.23,5.21) v1(31.29,11.48) v1(31.38,34.28) v1(31.66,41.19) v1(31.83,44.5) v1(31.96,34.98) v1(32.11,5.23) v1(32.19,41.76) v1(32.18,11.41) v1(32.29,43.59) v1(32.31,10.57) v1(32.31,9.81) v1(32.76,44.33) v1(32.91,41.09) v1(33.05,43.21) v1(33.04,42.31) v1(33,35.23) v1(32.99,11.46) v1(32.99,10.59) v1(33.02,9.91) v1(33.02,9.15) v1(33.01,5.42)
VBAT: length 8.9
  TOP w0.229: U17.30 25.69,34.64 26.12,34.21 26.12,34.01 C247.1 27.36,33.35 27.47,33.24 R96.2 28.19,34.17 28.77,34.75 28.77,35.08 v1(29.49,35.8)
  BOTTOM w0.229: v1(29.49,35.8) 30.17,35.8 30.53,35.43 30.53,34.71 TP23.1
VBAT_IN: length 4.6
  BOTTOM w0.229: TP34.1 1.93,17.35 1.93,14.91 2.42,14.42 v1(2.42,14.22)
  vias: v1(2.42,13.59) v1(8.53,16.64) v1(8.53,16.1)
VBUS_IN: length 11.9
  L03_SIG1 w0.229: v1(2.36,16.05) 2.13,15.83 2.13,14.82 2.33,14.62 2.59,14.62 3.51,13.69 3.51,10.26 v1(2.52,9.27)
  BOTTOM w0.229: v1(2.36,16.05) 2.36,16.56 2.74,16.94 4.26,16.94 4.44,16.76 R4.2 R3.2
  vias: v1(1.63,9.27) v1(6.51,9.14) v1(7.35,9.12)
VCC_1V8: length 124.6
  TOP w0.229: 28.46,23.5 29.96,23.5 30.18,23.72 ; 28.46,23.5 28.46,22.28 28.32,22.14 28.32,21.87 28.09,21.64 27.86,21.64 C72.1 27.7,21.48 FB6.1 ; 28.46,23.5 25.79,23.5 25.48,23.18 C74.1 25.25,22.49 FB7.1 23.03,22.49 22.82,22.27 C119.1 19.6,22.24 18.99,22.24 U19.C1 ; v1(17.78,8.09) C76.1 18.55,8.86 19.19,9.5 FB8.1 ; v1(28.47,30.06) 28.56,30.15 29.35,30.15 29.92,29.57 30.59,29.57 ; FB9.1 16.67,13.02 17.09,12.6 17.41,12.6 17.64,12.37 17.64,11.89 17.87,11.66 C78.1 18.14,11.85 18.14,12.25 v1(18.12,12.27) ; 30.18,23.72 30.18,27.53 30.59,27.93 30.59,29.57 ; 30.18,23.72 30.59,23.32 30.59,15.82 v1(29.14,14.38) ; v1(31.22,35.33) 30.74,35.33 30.06,34.65 ; 30.59,29.57 30.59,34.12 30.06,34.65 ; 30.06,34.65 29.52,34.65 v1(29.51,34.63) ; R97.1 27.62,40.48 27.55,40.48 v1(27.51,40.51) ; v1(21.27,8.9) 20.44,9.73 C87.1 20.52,10.76 FB11.1
  L04_SIG2 w0.229: v1(8.92,44.53) 8.92,44.27 9.15,44.04 v1(13.85,44.04) ; v1(31.22,35.33) 30.84,35.71 30.84,36.2 30.05,36.98 30.05,39.88 29.45,40.48 27.55,40.48 v1(27.51,40.51) ; v1(29.14,14.38) 29.14,13.36 27.54,11.76 25.87,11.76 23.9,13.73 23.9,14.01 23.87,14.03 23.87,14.06 23.64,14.29 21.66,14.29 v1(21.29,13.92)
  BOTTOM w0.203: R277.1 8.87,30.28 9.13,30.28 9.31,30.1 9.31,29.84 9.69,29.46 13.42,29.46 13.8,29.84 14.92,29.84 15.03,29.74 R278.1
  BOTTOM w0.229: v1(8.92,44.53) 8.92,44.11 9.44,43.59 J15.2 ; FB12.1 17.2,14.59 17.2,13.59 16.79,13.18 v1(15.76,13.18) ; 16.29,29.32 15.03,29.32 R278.1 ; 16.29,29.32 16.29,30.79 R84.1 ; 16.29,29.32 17.52,29.32 18.12,29.92 19.61,29.92 19.65,29.88 20,29.88 20.03,29.92 20.94,29.92 21.31,30.29 21.98,30.29 22.5,29.77 25.06,29.77 25.23,29.6 25.97,29.6 26.29,29.91 28.32,29.91 28.34,29.94 v1(28.47,30.06) C93.1 C92.1 28.45,31.38 U7.8 ; v1(27.51,40.51) 27.51,40.51 26.48,40.51 25.92,41.07 21.29,41.07 20.94,41.43 15,41.43 14.69,41.73 14.69,42.55 13.85,43.39 v1(13.85,44.04) ; R85.1 v1(29.51,34.63)
  vias: v1(21.29,13.39)
